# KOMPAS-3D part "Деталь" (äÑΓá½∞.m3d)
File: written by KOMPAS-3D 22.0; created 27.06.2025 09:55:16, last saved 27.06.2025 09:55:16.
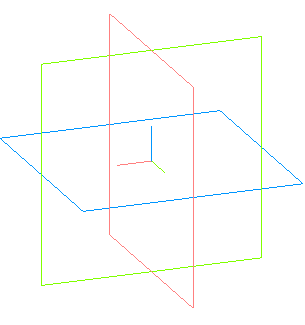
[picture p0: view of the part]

Document properties: Автор: Helen; Полное имя файла: D:\MY\WORK\MPEI\ППЭ_2025-2026\Варианты\Вар 11 СБ\Деталь.m3d

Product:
- Part/product: Деталь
